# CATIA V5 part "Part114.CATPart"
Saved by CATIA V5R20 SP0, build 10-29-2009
Part number: FA 063200-3
Revision: ANY
Definition: UNKNOWN
Nomenclature: FA 063200-3
Source: Unknown
Bounding box of the stored display mesh (mm): x -2.109 to 2.109, y -2.45 to 2.45, z -2 to 2
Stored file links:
  C:\Users\Utente\Desktop\IO LAVORO\3D X SITO CF\CUMSA\3D files FA\FA 063212-21\Part114.CATPart

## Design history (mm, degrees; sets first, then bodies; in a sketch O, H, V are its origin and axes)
Body1 "Chaflán4" (main body)
  Solid1: solid without history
